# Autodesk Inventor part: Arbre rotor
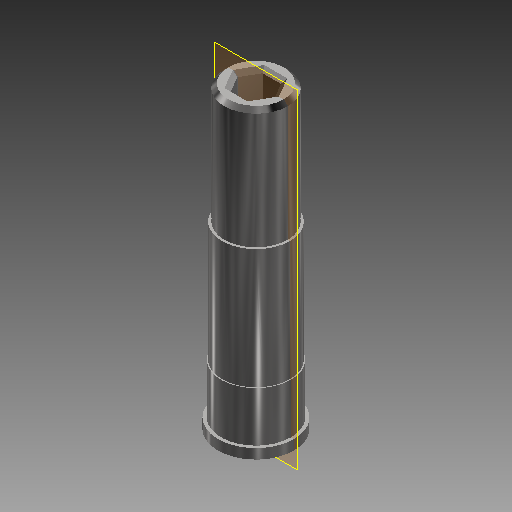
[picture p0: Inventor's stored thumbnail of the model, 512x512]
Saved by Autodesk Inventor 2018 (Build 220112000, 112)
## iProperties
Created: 2015-03
Part Number: Arbre rotor
Material: Acier, carbone
Document SubType Name: Modeling
Designer: pleblanc
Density: 7.87 g/cm^3
Mass: 125.477 g
Surface Area: 47.0831 cm^2
Volume: 15.9438 cm^3
Appearance: Acier - Poli
Author: pleblanc
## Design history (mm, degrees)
sketch "Esquisse1"
  geometry: L1 (0.037, 38.943)-(7.987, 38.943); L2 (7.987, 38.943)-(7.987, 8.943); L3 (7.987, 8.943)-(8.537, 8.943); L4 (8.537, 8.943)-(8.537, -21.057); L5 (8.537, -21.057)-(8.787, -21.057); L6 (8.787, -21.057)-(8.787, -33.557); L7 (8.787, -33.557)-(9.537, -33.557); L8 (9.537, -33.557)-(9.537, -36.057); L9 (9.537, -36.057)-(0.037, -36.057); L10 (0.037, -36.057)-(0.037, 38.943); 1 further point
  constraints: 20 end point, 5 parallel, 4 perpendicular, 1 horizontal
  dimensions: "d0" = 7.95 distance of L1.start L1.end; "d3" = 2.5 distance of L7.end L8.end; "d4" = 30 distance of L3.end L4.end; "d5" = 12.5 distance of L5.end L6.end; "d6" = 17 diameter of L4 L10; "d7" = 17.5 diameter of L6 L10; "d8" = 19 diameter of L8 L10; "d9" = 75 distance of L9.end L1.start; "d10" = 15.9 diameter of L2 L10 (derived)
revolve "Révolution1" sketch "Esquisse1" stored, may be unused: angle "d11" = 90 deg
sketch "Esquisse2"
  geometry: L1 (2.273, 4)-(4.582, 0); L2 (4.582, 0)-(2.273, -4); L3 (2.273, -4)-(-2.346, -4); L4 (-2.346, -4)-(-4.655, 0); L5 (-4.655, 0)-(-2.346, 4); L6 (-2.346, 4)-(2.273, 4); 2 further points
  constraints: 12 end point, 1 coincident, 13 other
  dimensions: "d12" = 8 distance between parallel lines of L3 L6
extrude "Extrusion1" cut sketch "Esquisse2" distance "d13" = 9; taper "d14" = 0 deg
chamfer "Chanfrein1" distance "d15" = 1; stored, may be unused: second distance "d16" = 2, angle "d17" = 45 deg
node "Solide1"
